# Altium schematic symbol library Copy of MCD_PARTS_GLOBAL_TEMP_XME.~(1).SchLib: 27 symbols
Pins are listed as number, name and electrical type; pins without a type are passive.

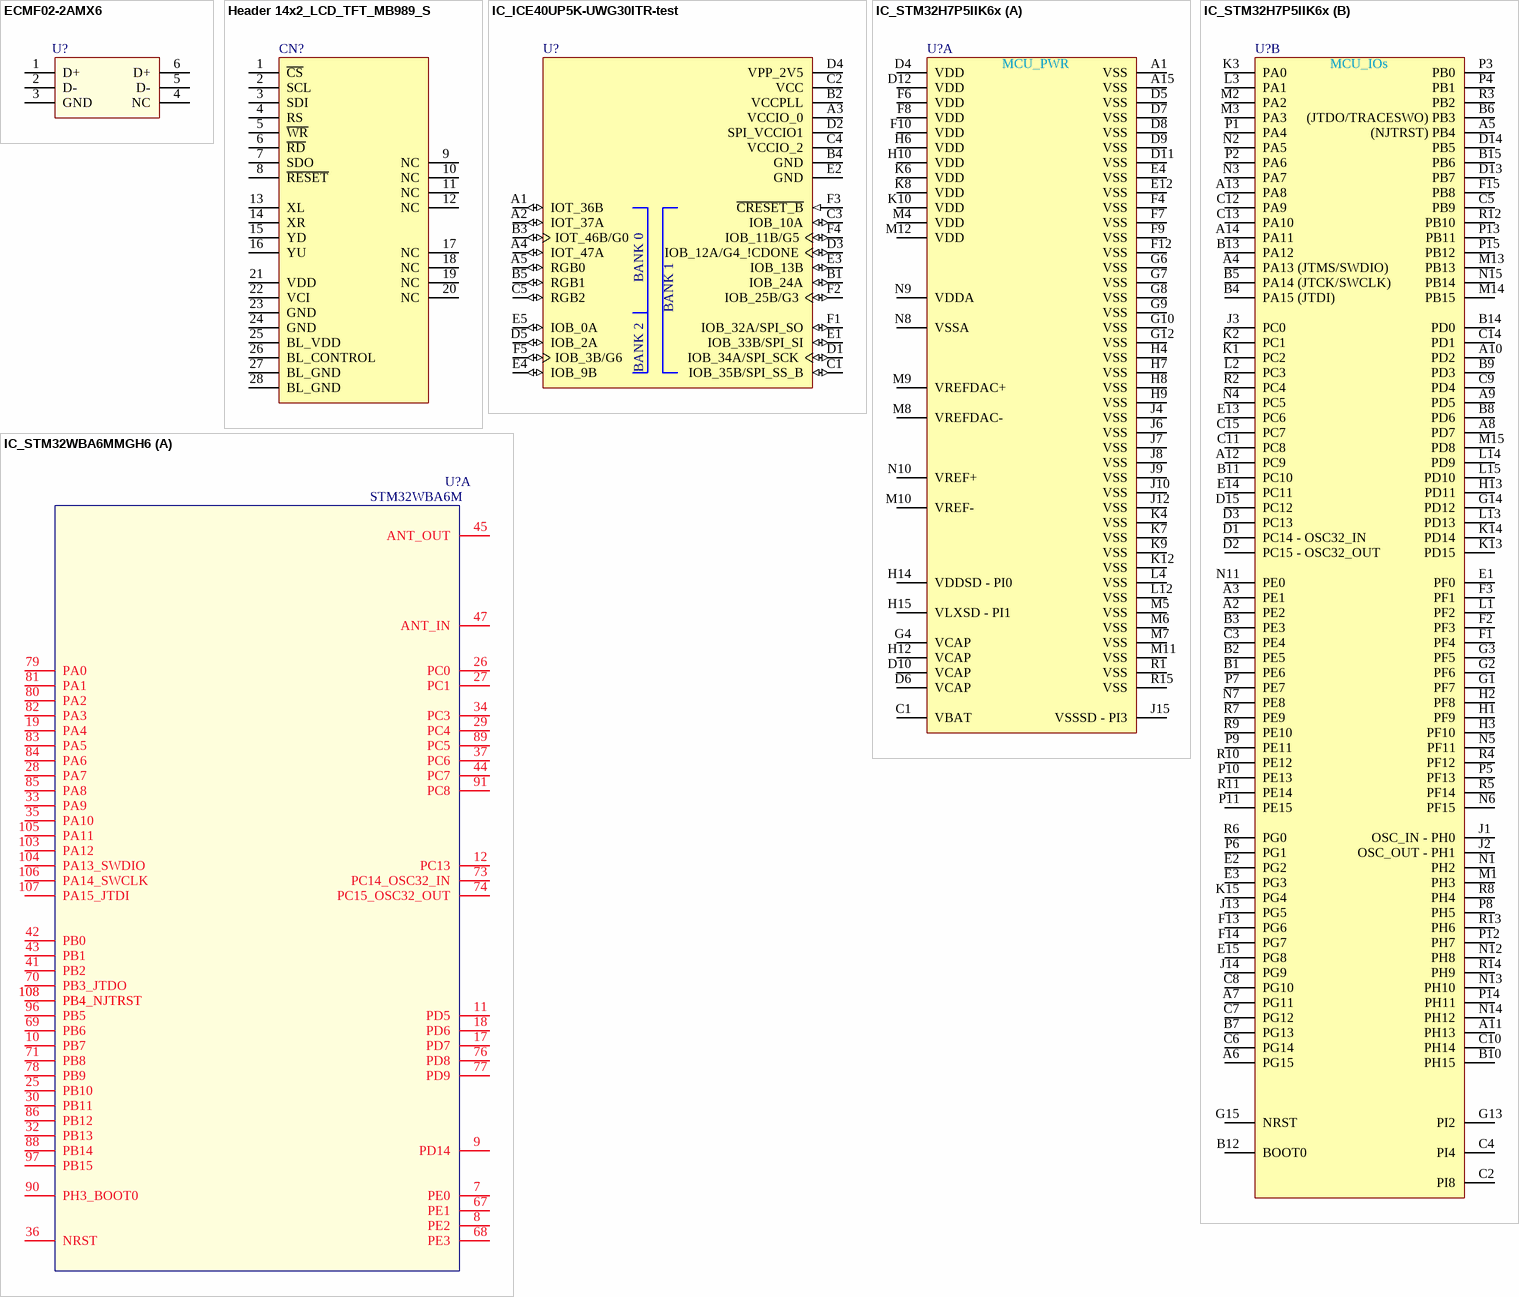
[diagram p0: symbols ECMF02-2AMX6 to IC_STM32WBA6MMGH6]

## ECMF02-2AMX6
designator U?
pins: 1 D+, 2 D-, 3 GND, 4 NC, 5 D-, 6 D+

## Header 14x2_LCD_TFT_MB989_S
designator CN?
pins: 1 ~{CS}, 2 SCL, 3 SDI, 4 RS, 5 ~{WR}, 6 ~{RD}, 7 SDO, 8 ~{RESET}, 9 NC, 10 NC, 11 NC, 12 NC, 13 XL, 14 XR, 15 YD, 16 YU, 17 NC, 18 NC, 19 NC, 20 NC, 21 VDD, 22 VCI, 23 GND, 24 GND, 25 BL_VDD, 26 BL_CONTROL, 27 BL_GND, 28 BL_GND
1 alternate drawing of the same symbol

## IC_ICE40UP5K-UWG30ITR-test
designator U?
Manufacturer: LATTICE SEMICONDUCTOR; Value: ICE40UP5K-UWG30ITR
footprint Model Name (Footprint not found)
footprint Model Name (Footprint not found)
footprint Model Name (Footprint not found)
pins: A1 IOT_36B (io), A2 IOT_37A (io), A3 VCCIO_0, A4 IOT_47A (io), A5 RGB0 (io), B1 IOB_24A (io), B2 VCCPLL, B3 IOT_46B/G0 (io), B4 GND, B5 RGB1 (io), C1 IOB_35B/SPI_SS_B (io), C2 VCC, C3 IOB_10A (io), C4 VCCIO_2, C5 RGB2 (io), D1 IOB_34A/SPI_SCK (io), D2 SPI_VCCIO1, D3 IOB_12A/G4_!CDONE (io), D4 VPP_2V5, D5 IOB_2A (io), E1 IOB_33B/SPI_SI (io), E2 GND, E3 IOB_13B (io), E4 IOB_9B (io), E5 IOB_0A (io), F1 IOB_32A/SPI_SO (io), F2 IOB_25B/G3 (io), F3 ~{CRESET_B} (in), F4 IOB_11B/G5 (io), F5 IOB_3B/G6 (io)

## IC_STM32H7P5IIK6x
designator U?
part A pins: A1 VSS, A15 VSS, C1 VBAT, D4 VDD, D5 VSS, D6 VCAP, D7 VSS, D8 VSS, D9 VSS, D10 VCAP, D11 VSS, D12 VDD, E4 VSS, E12 VSS, F4 VSS, F6 VDD, F7 VSS, F8 VDD, F9 VSS, F10 VDD, F12 VSS, G4 VCAP, G6 VSS, G7 VSS, G8 VSS, G9 VSS, G10 VSS, G12 VSS, H4 VSS, H6 VDD, H7 VSS, H8 VSS, H9 VSS, H10 VDD, H12 VCAP, H14 VDDSD - PI0, H15 VLXSD - PI1, J4 VSS, J6 VSS, J7 VSS, J8 VSS, J9 VSS, J10 VSS, J12 VSS, J15 VSSSD - PI3, K4 VSS, K6 VDD, K7 VSS, K8 VDD, K9 VSS, K10 VDD, K12 VSS, L4 VSS, L12 VSS, M4 VDD, M5 VSS, M6 VSS, M7 VSS, M8 VREFDAC-, M9 VREFDAC+, M10 VREF-, M11 VSS, M12 VDD, N8 VSSA, N9 VDDA, N10 VREF+, R1 VSS, R15 VSS
part B pins: A2 PE2, A3 PE1, A4 PA13 (JTMS/SWDIO), A5 (NJTRST) PB4, A6 PG15, A7 PG11, A8 PD7, A9 PD5, A10 PD2, A11 PH13, A12 PC9, A13 PA8, A14 PA11, B1 PE6, B2 PE5, B3 PE3, B4 PA15 (JTDI), B5 PA14 (JTCK/SWCLK), B6 (JTDO/TRACESWO) PB3, B7 PG13, B8 PD6, B9 PD3, B10 PH15, B11 PC10, B12 BOOT0, B13 PA12, B14 PD0, B15 PB6, C2 PI8, C3 PE4, C4 PI4, C5 PB9, C6 PG14, C7 PG12, C8 PG10, C9 PD4, C10 PH14, C11 PC8, C12 PA9, C13 PA10, C14 PD1, C15 PC7, D1 PC14 - OSC32_IN, D2 PC15 - OSC32_OUT, D3 PC13, D13 PB7, D14 PB5, D15 PC12, E1 PF0, E2 PG2, E3 PG3, E13 PC6, E14 PC11, E15 PG8, F1 PF4, F2 PF3, F3 PF1, F13 PG6, F14 PG7, F15 PB8, G1 PF7, G2 PF6, G3 PF5, G13 PI2, G14 PD12, G15 NRST, H1 PF9, H2 PF8, H3 PF10, H13 PD11, J1 OSC_IN - PH0, J2 OSC_OUT - PH1, J3 PC0, J13 PG5, J14 PG9, K1 PC2, K2 PC1, K3 PA0, K13 PD15, K14 PD14, K15 PG4, L1 PF2, L2 PC3, L3 PA1, L13 PD13, L14 PD9, L15 PD10, M1 PH3, M2 PA2, M3 PA3, M13 PB13, M14 PB15, M15 PD8, N1 PH2, N2 PA5, N3 PA7, N4 PC5, N5 PF11, N6 PF15, N7 PE8, N11 PE0, N12 PH8, N13 PH10, N14 PH12, N15 PB14, P1 PA4, P2 PA6, P3 PB0, P4 PB1, P5 PF13, P6 PG1, P7 PE7, P8 PH5, P9 PE11, P10 PE13, P11 PE15, P12 PH7, P13 PB11, P14 PH11, P15 PB12, R2 PC4, R3 PB2, R4 PF12, R5 PF14, R6 PG0, R7 PE9, R8 PH4, R9 PE10, R10 PE12, R11 PE14, R12 PB10, R13 PH6, R14 PH9
1 alternate drawing of the same symbol

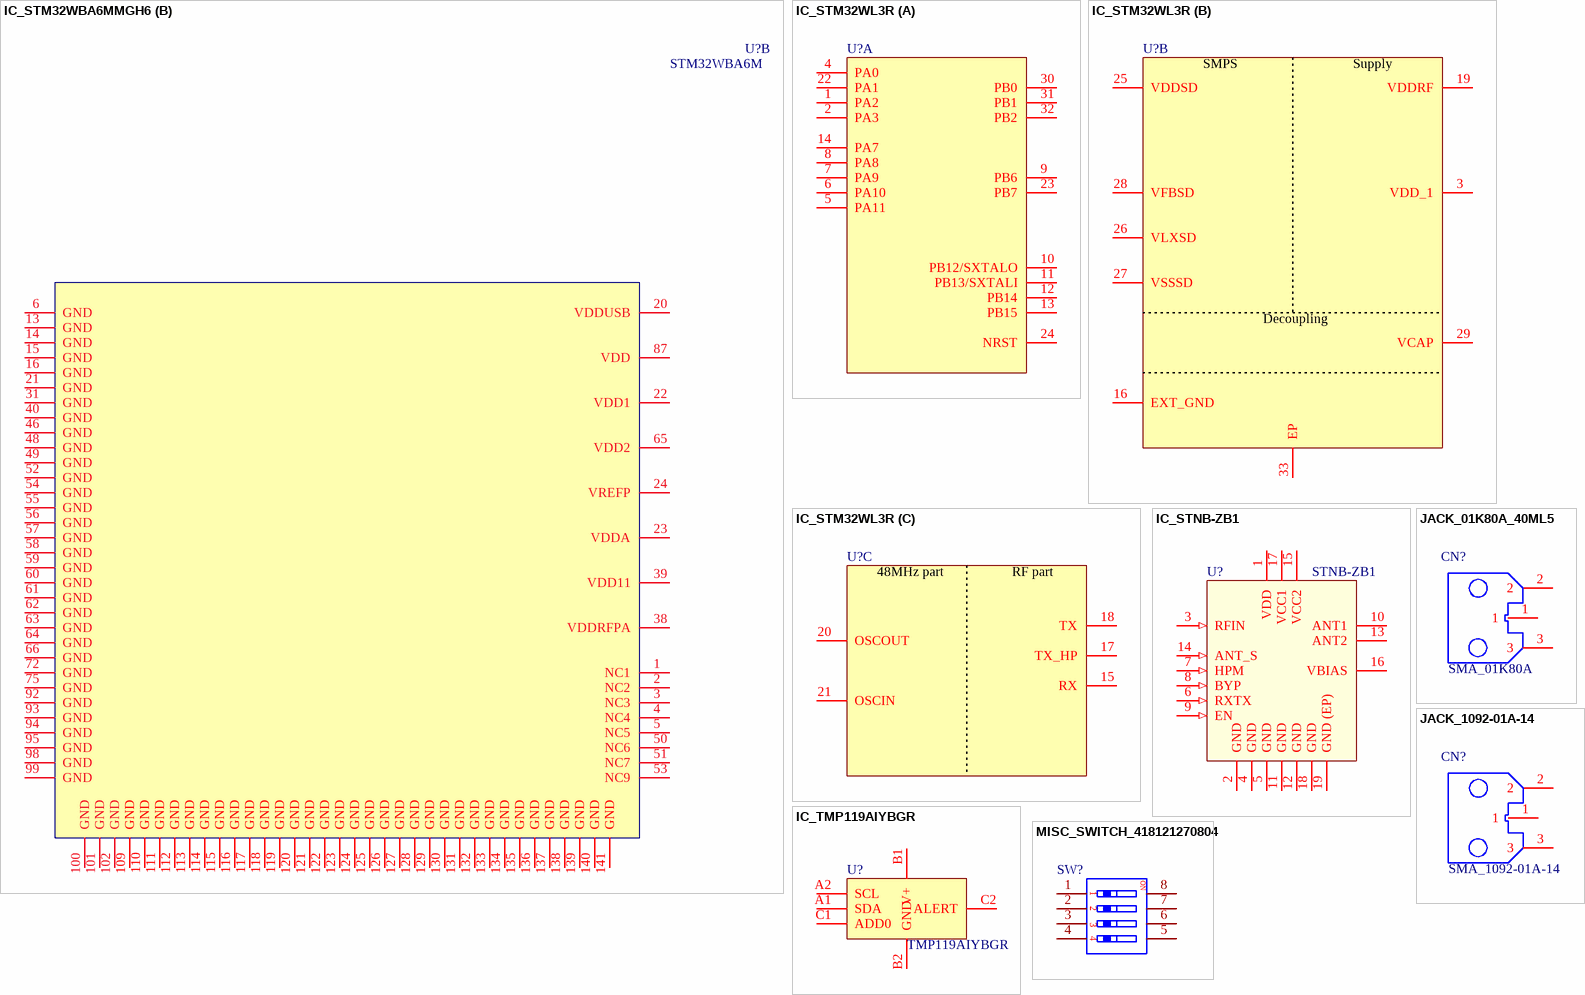
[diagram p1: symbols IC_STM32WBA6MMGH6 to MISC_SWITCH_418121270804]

## IC_STM32WBA6MMGH6
designator U?, comment STM32WBA6M
STM32WBA6M module; Internal_Part_Number: MCD-04297; Manufacturer: STMICROELECTRONICS; Manufacturer_Part_Number: STM32WBA6MMGH6; ECCN_EU: NEC; ECCN_US: EAR99
footprint STM32WBA6M (Footprint not found)
part A pins: 7 PE0, 8 PE2, 9 PD14, 10 PB7, 11 PD5, 12 PC13, 17 PD7, 18 PD6, 19 PA4, 25 PB10, 26 PC0, 27 PC1, 28 PA7, 29 PC4, 30 PB11, 32 PB13, 33 PA9, 34 PC3, 35 PA10, 36 NRST, 37 PC6, 41 PB2, 42 PB0, 43 PB1, 44 PC7, 45 ANT_OUT, 47 ANT_IN, 67 PE1, 68 PE3, 69 PB6, 70 PB3_JTDO, 71 PB8, 73 PC14_OSC32_IN, 74 PC15_OSC32_OUT, 76 PD8, 77 PD9, 78 PB9, 79 PA0, 80 PA2, 81 PA1, 82 PA3, 83 PA5, 84 PA6, 85 PA8, 86 PB12, 88 PB14, 89 PC5, 90 PH3_BOOT0, 91 PC8, 96 PB5, 97 PB15, 103 PA12, 104 PA13_SWDIO, 105 PA11, 106 PA14_SWCLK, 107 PA15_JTDI, 108 PB4_NJTRST
part B pins: 1 NC1, 2 NC2, 3 NC3, 4 NC4, 5 NC5, 6 GND, 13 GND, 14 GND, 15 GND, 16 GND, 20 VDDUSB, 21 GND, 22 VDD1, 23 VDDA, 24 VREFP, 31 GND, 38 VDDRFPA, 39 VDD11, 40 GND, 46 GND, 48 GND, 49 GND, 50 NC6, 51 NC7, 52 GND, 53 NC9, 54 GND, 55 GND, 56 GND, 57 GND, 58 GND, 59 GND, 60 GND, 61 GND, 62 GND, 63 GND, 64 GND, 65 VDD2, 66 GND, 72 GND, 75 GND, 87 VDD, 92 GND, 93 GND, 94 GND, 95 GND, 98 GND, 99 GND, 100 GND, 101 GND, 102 GND, 109 GND, 110 GND, 111 GND, 112 GND, 113 GND, 114 GND, 115 GND, 116 GND, 117 GND, 118 GND, 119 GND, 120 GND, 121 GND, 122 GND, 123 GND, 124 GND, 125 GND, 126 GND, 127 GND, 128 GND, 129 GND, 130 GND, 131 GND, 132 GND, 133 GND, 134 GND, 135 GND, 136 GND, 137 GND, 138 GND, 139 GND, 140 GND, 141 GND

## IC_STM32WL3R
designator U?
part A pins: 1 PA2, 2 PA3, 4 PA0, 5 PA11, 6 PA10, 7 PA9, 8 PA8, 9 PB6, 10 PB12/SXTALO, 11 PB13/SXTALI, 12 PB14, 13 PB15, 14 PA7, 22 PA1, 23 PB7, 24 NRST, 30 PB0, 31 PB1, 32 PB2
part B pins: 3 VDD_1, 16 EXT_GND, 19 VDDRF, 25 VDDSD, 26 VLXSD, 27 VSSSD, 28 VFBSD, 29 VCAP, 33 EP
part C pins: 15 RX, 17 TX_HP, 18 TX, 20 OSCOUT, 21 OSCIN

## IC_STNB-ZB1
designator U?  value STNB-ZB1
pins: 1 VDD (power), 2 GND, 3 RFIN (in), 4 GND, 5 GND, 6 RXTX (in), 7 HPM (in), 8 BYP (in), 9 EN (in), 10 ANT1, 11 GND, 12 GND, 13 ANT2, 14 ANT_S (in), 15 VCC2, 16 VBIAS, 17 VCC1 (power), 18 GND, 19 GND (EP)
1 alternate drawing of the same symbol

## IC_TMP119AIYBGR
designator U?, comment value TMP119AIYBGR  (hidden comment: SN74AUC1G17DBVR)
pins: A1 SDA, A2 SCL, B1 V+, B2 GND, C1 ADD0, C2 ALERT (oc)

## JACK_01K80A_40ML5
designator CN?, comment SMA_01K80A
PCB connector 30° 1mm connector
footprint Model Name (Footprint not found)
footprint Rosenberger_08K80F (RF conn 1.85mm)
footprint Rosenberger_08K80F (RF conn 1.85mm)
footprint Rosenberger_08K80F (RF conn 1.85mm)
footprint Rosenberger_08K80F (RF conn 1.85mm)
footprint Rosenberger_08K80F (RF conn 1.85mm)
footprint Rosenberger_08K80F_v2 (RF conn 1.85mm)
footprint Rosenberger_08K80F_v2 (RF conn 1.85mm)
footprint Rosenberger_08K80F_v2 (RF conn 1.85mm)
footprint Rosenberger_08K80F_v2 (RF conn 1.85mm)
footprint Rosenberger_08K80F_v2 (RF conn 1.85mm)
footprint Rosenberger_08K80F_v2 (RF conn 1.85mm)
footprint Rosenberger_08K80F_v2 (RF conn 1.85mm)
footprint Rosenberger_08K80F_v2 (RF conn 1.85mm)
footprint Rosenberger_08K80F_v2 (RF conn 1.85mm)
footprint Rosenberger_08K80F_v2 (RF conn 1.85mm)
footprint Rosenberger_08K80F_v2 (RF conn 1.85mm)
footprint Rosenberger_08K80F_v2 (RF conn 1.85mm)
footprint Rosenberger_08K80F_v2 (RF conn 1.85mm)
footprint Rosenberger_08K80F_v2 (RF conn 1.85mm)
footprint Rosenberger_08K80F_v2 (RF conn 1.85mm)
footprint Rosenberger_08K80F_v2 (RF conn 1.85mm)
footprint Rosenberger_08K80F_v2 (RF conn 1.85mm)
footprint Rosenberger_08K80F_v2 (RF conn 1.85mm)
footprint Rosenberger_08K80F_v2 (RF conn 1.85mm)
footprint Rosenberger_08K80F_v2 (RF conn 1.85mm)
footprint Rosenberger_08K80F_v2 (RF conn 1.85mm)
footprint Rosenberger_08K80F_v2 (RF conn 1.85mm)
footprint Rosenberger_08K80F_v2 (RF conn 1.85mm)
footprint Rosenberger_08K80F_v2 (RF conn 1.85mm)
pins: 1, 2, 3

## JACK_1092-01A-14
designator CN?, comment SMA_1092-01A-14
footprint Model Name (Footprint not found)
footprint Rosenberger_08K80F (RF conn 1.85mm)
footprint Rosenberger_08K80F (RF conn 1.85mm)
footprint Rosenberger_08K80F (RF conn 1.85mm)
footprint Rosenberger_08K80F (RF conn 1.85mm)
footprint Rosenberger_08K80F (RF conn 1.85mm)
footprint Rosenberger_08K80F_v2 (RF conn 1.85mm)
footprint Rosenberger_08K80F_v2 (RF conn 1.85mm)
footprint Rosenberger_08K80F_v2 (RF conn 1.85mm)
footprint Rosenberger_08K80F_v2 (RF conn 1.85mm)
footprint Rosenberger_08K80F_v2 (RF conn 1.85mm)
footprint Rosenberger_08K80F_v2 (RF conn 1.85mm)
footprint Rosenberger_08K80F_v2 (RF conn 1.85mm)
footprint Rosenberger_08K80F_v2 (RF conn 1.85mm)
footprint Rosenberger_08K80F_v2 (RF conn 1.85mm)
footprint Rosenberger_08K80F_v2 (RF conn 1.85mm)
footprint Rosenberger_08K80F_v2 (RF conn 1.85mm)
footprint Rosenberger_08K80F_v2 (RF conn 1.85mm)
footprint Rosenberger_08K80F_v2 (RF conn 1.85mm)
footprint Rosenberger_08K80F_v2 (RF conn 1.85mm)
footprint Rosenberger_08K80F_v2 (RF conn 1.85mm)
footprint Rosenberger_08K80F_v2 (RF conn 1.85mm)
footprint Rosenberger_08K80F_v2 (RF conn 1.85mm)
footprint Rosenberger_08K80F_v2 (RF conn 1.85mm)
footprint Rosenberger_08K80F_v2 (RF conn 1.85mm)
footprint Rosenberger_08K80F_v2 (RF conn 1.85mm)
footprint Rosenberger_08K80F_v2 (RF conn 1.85mm)
footprint Rosenberger_08K80F_v2 (RF conn 1.85mm)
footprint Rosenberger_08K80F_v2 (RF conn 1.85mm)
footprint Rosenberger_08K80F_v2 (RF conn 1.85mm)
pins: 1, 2, 3

## MISC_SWITCH_418121270804
designator SW?
Switch 4 slides DIP, SPST, 24V, 25mA, 9.8x11.1mm
pins: 1, 2, 3, 4, 5, 6, 7, 8

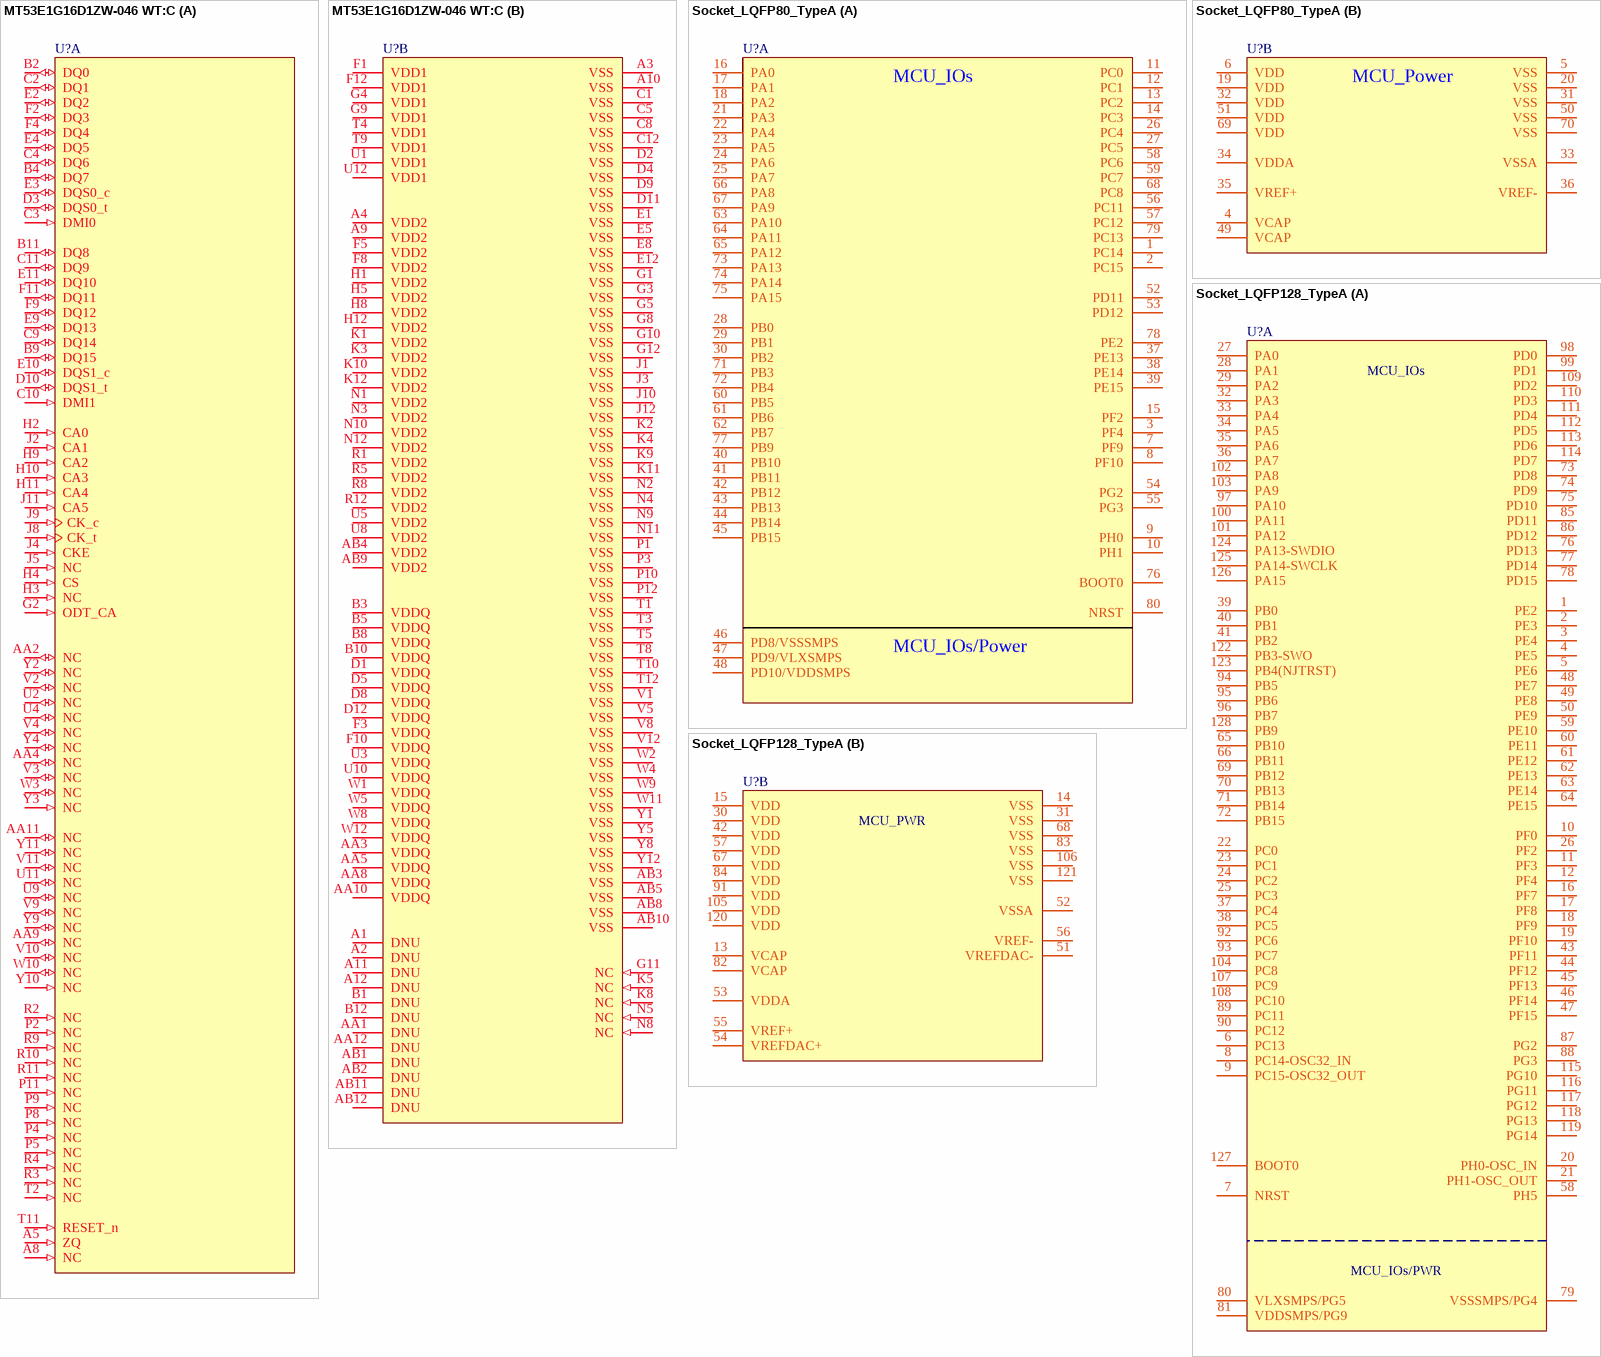
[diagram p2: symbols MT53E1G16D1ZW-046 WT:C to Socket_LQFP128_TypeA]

## MT53E1G16D1ZW-046 WT:C
designator U?
part A pins: A5 ZQ (in) "External impedance (240 ohm): This signal is used to calibrate the device output impedance.", A8 NC (in), AA2 NC (io) "Data input/output: Bidirectional data bus.", AA4 NC (io) "Data input/output: Bidirectional data bus.", AA9 NC (io) "Data input/output: Bidirectional data bus.", AA11 NC (io) "Data input/output: Bidirectional data bus.", B2 DQ0 (io) "Data input/output: Bidirectional data bus.", B4 DQ7 (io) "Data input/output: Bidirectional data bus.", B9 DQ15 (io) "Data input/output: Bidirectional data bus.", B11 DQ8 (io) "Data input/output: Bidirectional data bus.", C2 DQ1 (io) "Data input/output: Bidirectional data bus.", C3 DMI0 (in) "Input data mask: DM is an input mask signal for write data. Although DM ballsare input-only, the DM loading is designed to match that of DQ and DQS balls.DM[3:0] is DM for each of the four data bytes, respectively.", C4 DQ6 (io) "Data input/output: Bidirectional data bus.", C9 DQ14 (io) "Data input/output: Bidirectional data bus.", C10 DMI1 (in) "Input data mask: DM is an input mask signal for write data. Although DM ballsare input-only, the DM loading is designed to match that of DQ and DQS balls.DM[3:0] is DM for each of the four data bytes, respectively.", C11 DQ9 (io) "Data input/output: Bidirectional data bus.", D3 DQS0_t (io) "Data strobe: The data strobe is bidirectional (used for read and write data) andcomplementary (DQS and DQS#). It is edge-aligned output with read data andcentered input with write data. DQS[3:0]/DQS[3:0]# is DQS for each of (See Datasheet)", D10 DQS1_t (io) "Data strobe: The data strobe is bidirectional (used for read and write data) andcomplementary (DQS and DQS#). It is edge-aligned output with read data andcentered input with write data. DQS[3:0]/DQS[3:0]# is DQS for each of (See Datasheet)", E2 DQ2 (io) "Data input/output: Bidirectional data bus.", E3 DQS0_c (io) "Data strobe: The data strobe is bidirectional (used for read and write data) andcomplementary (DQS and DQS#). It is edge-aligned output with read data andcentered input with write data. DQS[3:0]/DQS[3:0]# is DQS for each of (See Datasheet)", E4 DQ5 (io) "Data input/output: Bidirectional data bus.", E9 DQ13 (io) "Data input/output: Bidirectional data bus.", E10 DQS1_c (io) "Data strobe: The data strobe is bidirectional (used for read and write data) andcomplementary (DQS and DQS#). It is edge-aligned output with read data andcentered input with write data. DQS[3:0]/DQS[3:0]# is DQS for each of (See Datasheet)", E11 DQ10 (io) "Data input/output: Bidirectional data bus.", F2 DQ3 (io) "Data input/output: Bidirectional data bus.", F4 DQ4 (io) "Data input/output: Bidirectional data bus.", F9 DQ12 (io) "Data input/output: Bidirectional data bus.", F11 DQ11 (io) "Data input/output: Bidirectional data bus.", G2 ODT_CA (in) "on die termination on CA", H2 CA0 (in) "Command/address inputs: Provide the command and address inputs accordingto the command truth table.", H3 NC (in), H4 CS (in) "Chip select: CS# is considered part of the command code and is sampled at therising edge of CK.", H9 CA2 (in) "Command/address inputs: Provide the command and address inputs accordingto the command truth table.", H10 CA3 (in) "Command/address inputs: Provide the command and address inputs accordingto the command truth table.", H11 CA4 (in) "Command/address inputs: Provide the command and address inputs accordingto the command truth table.", J2 CA1 (in) "Command/address inputs: Provide the command and address inputs accordingto the command truth table.", J4 CKE (in) "Clock enable: CKE HIGH activates and CKE LOW deactivates the internal clocksignals, input buffers, and output drivers. Power-saving modes are entered andexited via CKE transitions. CKE is considered part of the command code. (See Datasheet)", J5 NC (in), J8 CK_t (in) "Clock: CK and CK# are differential clock inputs. All CA inputs are sampled onboth rising and falling edges of CK. CS and CKE inputs are sampled at the risingedge of CK. AC timings are referenced to clock.", J9 CK_c (in) "Clock: CK and CK# are differential clock inputs. All CA inputs are sampled onboth rising and falling edges of CK. CS and CKE inputs are sampled at the risingedge of CK. AC timings are referenced to clock.", J11 CA5 (in) "Command/address inputs: Provide the command and address inputs accordingto the command truth table.", P2 NC (in) "Command/address inputs: Provide the command and address inputs accordingto the command truth table.", P4 NC (in) "Clock enable: CKE HIGH activates and CKE LOW deactivates the internal clocksignals, input buffers, and output drivers. Power-saving modes are entered andexited via CKE transitions. CKE is considered part of the command code. (See Datasheet)", P5 NC (in), P8 NC (in) "Clock: CK and CK# are differential clock inputs. All CA inputs are sampled onboth rising and falling edges of CK. CS and CKE inputs are sampled at the risingedge of CK. AC timings are referenced to clock.", P9 NC (in) "Clock: CK and CK# are differential clock inputs. All CA inputs are sampled onboth rising and falling edges of CK. CS and CKE inputs are sampled at the risingedge of CK. AC timings are referenced to clock.", P11 NC (in) "Command/address inputs: Provide the command and address inputs accordingto the command truth table.", R2 NC (in) "Command/address inputs: Provide the command and address inputs accordingto the command truth table.", R3 NC (in), R4 NC (in) "Chip select: CS# is considered part of the command code and is sampled at therising edge of CK.", R9 NC (in) "Command/address inputs: Provide the command and address inputs accordingto the command truth table.", R10 NC (in) "Command/address inputs: Provide the command and address inputs accordingto the command truth table.", R11 NC (in) "Command/address inputs: Provide the command and address inputs accordingto the command truth table.", T2 NC (in) "on die termination on CA", T11 RESET_n (in) "Reset active low", U2 NC (io) "Data input/output: Bidirectional data bus.", U4 NC (io) "Data input/output: Bidirectional data bus.", U9 NC (io) "Data input/output: Bidirectional data bus.", U11 NC (io) "Data input/output: Bidirectional data bus.", V2 NC (io) "Data input/output: Bidirectional data bus.", V3 NC (io) "Data strobe: The data strobe is bidirectional (used for read and write data) andcomplementary (DQS and DQS#). It is edge-aligned output with read data andcentered input with write data. DQS[3:0]/DQS[3:0]# is DQS for each of (See Datasheet)", V4 NC (io) "Data input/output: Bidirectional data bus.", V9 NC (io) "Data input/output: Bidirectional data bus.", V10 NC (io) "Data strobe: The data strobe is bidirectional (used for read and write data) andcomplementary (DQS and DQS#). It is edge-aligned output with read data andcentered input with write data. DQS[3:0]/DQS[3:0]# is DQS for each of (See Datasheet)", V11 NC (io) "Data input/output: Bidirectional data bus.", W3 NC (io) "Data strobe: The data strobe is bidirectional (used for read and write data) andcomplementary (DQS and DQS#). It is edge-aligned output with read data andcentered input with write data. DQS[3:0]/DQS[3:0]# is DQS for each of (See Datasheet)", W10 NC (io) "Data strobe: The data strobe is bidirectional (used for read and write data) andcomplementary (DQS and DQS#). It is edge-aligned output with read data andcentered input with write data. DQS[3:0]/DQS[3:0]# is DQS for each of (See Datasheet)", Y2 NC (io) "Data input/output: Bidirectional data bus.", Y3 NC (in) "Input data mask: DM is an input mask signal for write data. Although DM ballsare input-only, the DM loading is designed to match that of DQ and DQS balls.DM[3:0] is DM for each of the four data bytes, respectively.", Y4 NC (io) "Data input/output: Bidirectional data bus.", Y9 NC (io) "Data input/output: Bidirectional data bus.", Y10 NC (in) "Input data mask: DM is an input mask signal for write data. Although DM ballsare input-only, the DM loading is designed to match that of DQ and DQS balls.DM[3:0] is DM for each of the four data bytes, respectively.", Y11 NC (io) "Data input/output: Bidirectional data bus."
part B pins: A1 DNU "Do not use: Must be grounded or left floating.", A2 DNU "Do not use: Must be grounded or left floating.", A3 VSS (power) "Common ground.", A4 VDD2 (power) "Core power: Supply 2.", A9 VDD2 (power) "Core power: Supply 2.", A10 VSS (power) "Common ground.", A11 DNU "Do not use: Must be grounded or left floating.", A12 DNU "Do not use: Must be grounded or left floating.", AA1 DNU "Do not use: Must be grounded or left floating.", AA3 VDDQ (power) "DQ power supply: Isolated on the die for improved noise immunity.", AA5 VDDQ (power) "DQ power supply: Isolated on the die for improved noise immunity.", AA8 VDDQ (power) "DQ power supply: Isolated on the die for improved noise immunity.", AA10 VDDQ (power) "DQ power supply: Isolated on the die for improved noise immunity.", AA12 DNU "Do not use: Must be grounded or left floating.", AB1 DNU "Do not use: Must be grounded or left floating.", AB2 DNU "Do not use: Must be grounded or left floating.", AB3 VSS "Common ground.", AB4 VDD2 (power) "Core power: Supply 2.", AB5 VSS "Common ground.", AB8 VSS "Common ground.", AB9 VDD2 (power) "Core power: Supply 2.", AB10 VSS "Common ground.", AB11 DNU "Do not use: Must be grounded or left floating.", AB12 DNU "Do not use: Must be grounded or left floating.", B1 DNU "Do not use: Must be grounded or left floating.", B3 VDDQ (power) "DQ power supply: Isolated on the die for improved noise immunity.", B5 VDDQ (power) "DQ power supply: Isolated on the die for improved noise immunity.", B8 VDDQ (power) "DQ power supply: Isolated on the die for improved noise immunity.", B10 VDDQ (power) "DQ power supply: Isolated on the die for improved noise immunity.", B12 DNU "Do not use: Must be grounded or left floating.", C1 VSS (power) "Common ground.", C5 VSS (power) "Common ground.", C8 VSS (power) "Common ground.", C12 VSS (power) "Common ground.", D1 VDDQ (power) "DQ power supply: Isolated on the die for improved noise immunity.", D2 VSS (power) "Common ground.", D4 VSS (power) "Common ground.", D5 VDDQ (power) "DQ power supply: Isolated on the die for improved noise immunity.", D8 VDDQ (power) "DQ power supply: Isolated on the die for improved noise immunity.", D9 VSS (power) "Common ground.", D11 VSS (power) "Common ground.", D12 VDDQ (power) "DQ power supply: Isolated on the die for improved noise immunity.", E1 VSS (power) "Common ground.", E5 VSS (power) "Common ground.", E8 VSS (power) "Common ground.", E12 VSS (power) "Common ground.", F1 VDD1 (power) "Core power: Supply 1.", F3 VDDQ (power) "DQ power supply: Isolated on the die for improved noise immunity.", F5 VDD2 (power) "Core power: Supply 2.", F8 VDD2 (power) "Core power: Supply 2.", F10 VDDQ (power) "DQ power supply: Isolated on the die for improved noise immunity.", F12 VDD1 (power) "Core power: Supply 1.", G1 VSS (power) "Common ground.", G3 VSS (power) "Common ground.", G4 VDD1 (power) "Core power: Supply 1.", G5 VSS (power) "Common ground.", G8 VSS (power) "Common ground.", G9 VDD1 (power) "Core power: Supply 1.", G10 VSS (power) "Common ground.", G11 NC (in) "Not connected", G12 VSS (power) "Common ground.", H1 VDD2 (power) "Core power: Supply 2.", H5 VDD2 (power) "Core power: Supply 2.", H8 VDD2 (power) "Core power: Supply 2.", H12 VDD2 (power) "Core power: Supply 2.", J1 VSS (power) "Common ground.", J3 VSS (power) "Common ground.", J10 VSS (power) "Common ground.", J12 VSS (power) "Common ground.", K1 VDD2 (power) "Core power: Supply 2.", K2 VSS (power) "Common ground.", K3 VDD2 (power) "Core power: Supply 2.", K4 VSS (power) "Common ground.", K5 NC (in) "Not connected", K8 NC (in) "Not connected", K9 VSS (power) "Common ground.", K10 VDD2 (power) "Core power: Supply 2.", K11 VSS "Common ground.", K12 VDD2 (power) "Core power: Supply 2.", N1 VDD2 (power) "Core power: Supply 2.", N2 VSS "Common ground.", N3 VDD2 (power) "Core power: Supply 2.", N4 VSS "Common ground.", N5 NC (in) "Not connected", N8 NC (in) "Not connected", N9 VSS "Common ground.", N10 VDD2 (power) "Core power: Supply 2.", N11 VSS "Common ground.", N12 VDD2 (power) "Core power: Supply 2.", P1 VSS "Common ground.", P3 VSS (power) "Common ground.", P10 VSS (power) "Common ground.", P12 VSS "Common ground.", R1 VDD2 (power) "Core power: Supply 2.", R5 VDD2 (power) "Core power: Supply 2.", R8 VDD2 (power) "Core power: Supply 2.", R12 VDD2 (power) "Core power: Supply 2.", T1 VSS "Common ground.", T3 VSS "Common ground.", T4 VDD1 (power) "Core power: Supply 1.", T5 VSS "Common ground.", T8 VSS "Common ground.", T9 VDD1 (power) "Core power: Supply 1.", T10 VSS "Common ground.", T12 VSS "Common ground.", U1 VDD1 (power) "Core power: Supply 1.", U3 VDDQ (power) "DQ power supply: Isolated on the die for improved noise immunity.", U5 VDD2 (power) "Core power: Supply 2.", U8 VDD2 (power) "Core power: Supply 2.", U10 VDDQ (power) "DQ power supply: Isolated on the die for improved noise immunity.", U12 VDD1 (power) "Core power: Supply 1.", V1 VSS (power) "Common ground.", V5 VSS (power) "Common ground.", V8 VSS "Common ground.", V12 VSS "Common ground.", W1 VDDQ (power) "DQ power supply: Isolated on the die for improved noise immunity.", W2 VSS "Common ground.", W4 VSS "Common ground.", W5 VDDQ (power) "DQ power supply: Isolated on the die for improved noise immunity.", W8 VDDQ (power) "DQ power supply: Isolated on the die for improved noise immunity.", W9 VSS "Common ground.", W11 VSS "Common ground.", W12 VDDQ (power) "DQ power supply: Isolated on the die for improved noise immunity.", Y1 VSS "Common ground.", Y5 VSS "Common ground.", Y8 VSS "Common ground.", Y12 VSS "Common ground."

## Socket_LQFP80_TypeA
designator U?
part A pins: 1 PC14, 2 PC15, 3 PF4, 7 PF9, 8 PF10, 9 PH0, 10 PH1, 11 PC0, 12 PC1, 13 PC2, 14 PC3, 15 PF2, 16 PA0, 17 PA1, 18 PA2, 21 PA3, 22 PA4, 23 PA5, 24 PA6, 25 PA7, 26 PC4, 27 PC5, 28 PB0, 29 PB1, 30 PB2, 37 PE13, 38 PE14, 39 PE15, 40 PB10, 41 PB11, 42 PB12, 43 PB13, 44 PB14, 45 PB15, 46 PD8/VSSSMPS, 47 PD9/VLXSMPS, 48 PD10/VDDSMPS, 52 PD11, 53 PD12, 54 PG2, 55 PG3, 56 PC11, 57 PC12, 58 PC6, 59 PC7, 60 PB5, 61 PB6, 62 PB7, 63 PA10, 64 PA11, 65 PA12, 66 PA8, 67 PA9, 68 PC8, 71 PB3, 72 PB4, 73 PA13, 74 PA14, 75 PA15, 76 BOOT0, 77 PB9, 78 PE2, 79 PC13, 80 NRST
part B pins: 4 VCAP, 5 VSS, 6 VDD, 19 VDD, 20 VSS, 31 VSS, 32 VDD, 33 VSSA, 34 VDDA, 35 VREF+, 36 VREF-, 49 VCAP, 50 VSS, 51 VDD, 69 VDD, 70 VSS

## Socket_LQFP128_TypeA
designator U?
part A pins: 1 PE2, 2 PE3, 3 PE4, 4 PE5, 5 PE6, 6 PC13, 7 NRST, 8 PC14-OSC32_IN, 9 PC15-OSC32_OUT, 10 PF0, 11 PF3, 12 PF4, 16 PF7, 17 PF8, 18 PF9, 19 PF10, 20 PH0-OSC_IN, 21 PH1-OSC_OUT, 22 PC0, 23 PC1, 24 PC2, 25 PC3, 26 PF2, 27 PA0, 28 PA1, 29 PA2, 32 PA3, 33 PA4, 34 PA5, 35 PA6, 36 PA7, 37 PC4, 38 PC5, 39 PB0, 40 PB1, 41 PB2, 43 PF11, 44 PF12, 45 PF13, 46 PF14, 47 PF15, 48 PE7, 49 PE8, 50 PE9, 58 PH5, 59 PE10, 60 PE11, 61 PE12, 62 PE13, 63 PE14, 64 PE15, 65 PB10, 66 PB11, 69 PB12, 70 PB13, 71 PB14, 72 PB15, 73 PD8, 74 PD9, 75 PD10, 76 PD13, 77 PD14, 78 PD15, 79 VSSSMPS/PG4, 80 VLXSMPS/PG5, 81 VDDSMPS/PG9, 85 PD11, 86 PD12, 87 PG2, 88 PG3, 89 PC11, 90 PC12, 92 PC6, 93 PC7, 94 PB5, 95 PB6, 96 PB7, 97 PA10, 98 PD0, 99 PD1, 100 PA11, 101 PA12, 102 PA8, 103 PA9, 104 PC8, 107 PC9, 108 PC10, 109 PD2, 110 PD3, 111 PD4, 112 PD5, 113 PD6, 114 PD7, 115 PG10, 116 PG11, 117 PG12, 118 PG13, 119 PG14, 122 PB3-SWO, 123 PB4(NJTRST), 124 PA13-SWDIO, 125 PA14-SWCLK, 126 PA15, 127 BOOT0, 128 PB9
part B pins: 13 VCAP, 14 VSS, 15 VDD, 30 VDD, 31 VSS, 42 VDD, 51 VREFDAC-, 52 VSSA, 53 VDDA, 54 VREFDAC+, 55 VREF+, 56 VREF-, 57 VDD, 67 VDD, 68 VSS, 82 VCAP, 83 VSS, 84 VDD, 91 VDD, 105 VDD, 106 VSS, 120 VDD, 121 VSS

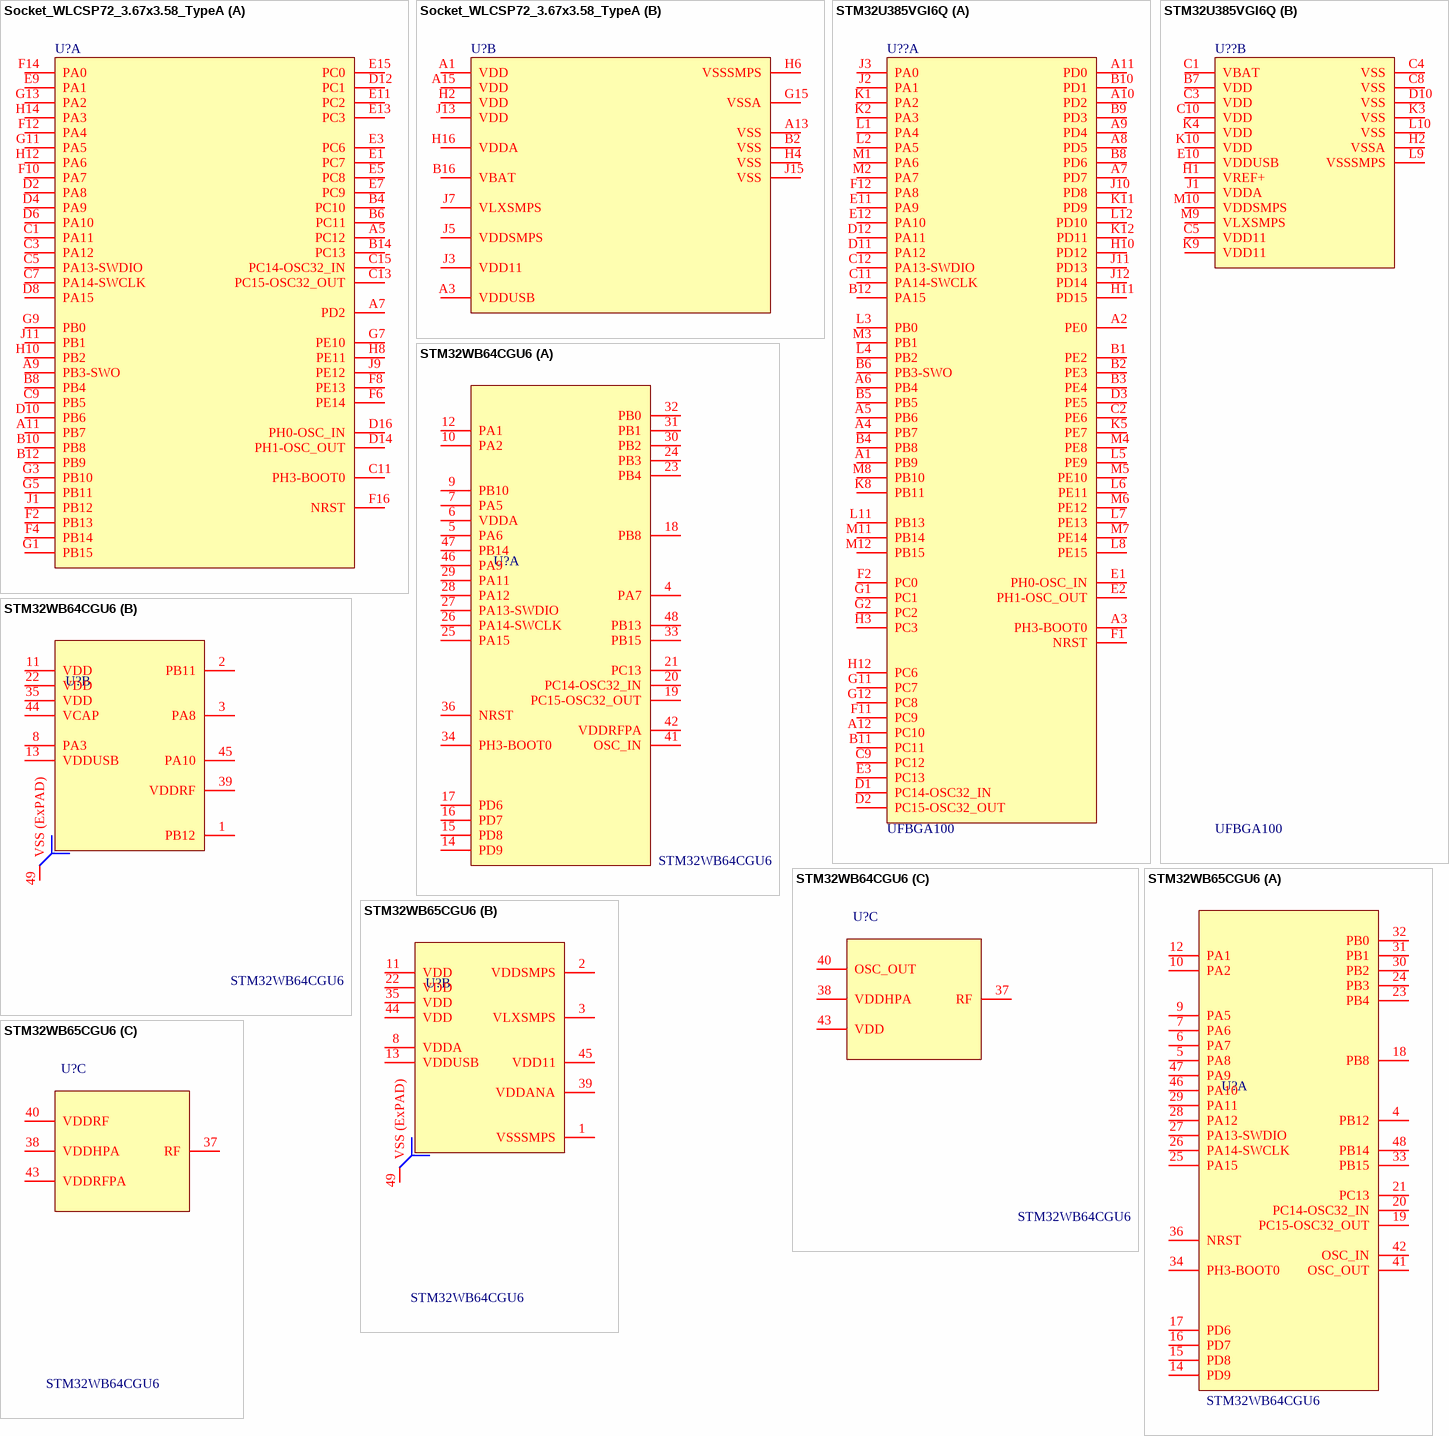
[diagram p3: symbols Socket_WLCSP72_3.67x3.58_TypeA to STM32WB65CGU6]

## Socket_WLCSP72_3.67x3.58_TypeA
designator U?
part A pins: A5 PC12, A7 PD2, A9 PB3-SWO, A11 PB7, B4 PC10, B6 PC11, B8 PB4, B10 PB8, B12 PB9, B14 PC13, C1 PA11, C3 PA12, C5 PA13-SWDIO, C7 PA14-SWCLK, C9 PB5, C11 PH3-BOOT0, C13 PC15-OSC32_OUT, C15 PC14-OSC32_IN, D2 PA8, D4 PA9, D6 PA10, D8 PA15, D10 PB6, D12 PC1, D14 PH1-OSC_OUT, D16 PH0-OSC_IN, E1 PC7, E3 PC6, E5 PC8, E7 PC9, E9 PA1, E11 PC2, E13 PC3, E15 PC0, F2 PB13, F4 PB14, F6 PE14, F8 PE13, F10 PA7, F12 PA4, F14 PA0, F16 NRST, G1 PB15, G3 PB10, G5 PB11, G7 PE10, G9 PB0, G11 PA5, G13 PA2, H8 PE11, H10 PB2, H12 PA6, H14 PA3, J1 PB12, J9 PE12, J11 PB1
part B pins: A1 VDD, A3 VDDUSB, A13 VSS, A15 VDD, B2 VSS, B16 VBAT, G15 VSSA, H2 VDD, H4 VSS, H6 VSSSMPS, H16 VDDA, J3 VDD11, J5 VDDSMPS, J7 VLXSMPS, J13 VDD, J15 VSS

## STM32U385VGI6Q
designator U??  value UFBGA100  (hidden comment: STM32U385VGI6Q)
MCU, ARM Cortex-M33 32-bit, 1MB Flash, 256KB SRAM, TrustZone and FPU, SMPS; Internal_Part_Number: MCD-03201; Part_Type: Socket_IC; Manufacturer_Part_Number: NP584-100-204; Manufacturer: YAMAICHI; Part_Preference: Recommended; Component_Country_Of_Origin: Unknown; ShowFields: YES; ID: 5317
part A pins: A1 PB9, A2 PE0, A3 PH3-BOOT0, A4 PB7, A5 PB6, A6 PB4, A7 PD7, A8 PD5, A9 PD4, A10 PD2, A11 PD0, A12 PC10, B1 PE2, B2 PE3, B3 PE4, B4 PB8, B5 PB5, B6 PB3-SWO, B8 PD6, B9 PD3, B10 PD1, B11 PC11, B12 PA15, C2 PE6, C9 PC12, C11 PA14-SWCLK, C12 PA13-SWDIO, D1 PC14-OSC32_IN, D2 PC15-OSC32_OUT, D3 PE5, D11 PA12, D12 PA11, E1 PH0-OSC_IN, E2 PH1-OSC_OUT, E3 PC13, E11 PA9, E12 PA10, F1 NRST, F2 PC0, F11 PC9, F12 PA8, G1 PC1, G2 PC2, G11 PC7, G12 PC8, H3 PC3, H10 PD12, H11 PD15, H12 PC6, J2 PA1, J3 PA0, J10 PD8, J11 PD13, J12 PD14, K1 PA2, K2 PA3, K5 PE7, K8 PB11, K11 PD9, K12 PD11, L1 PA4, L2 PA5, L3 PB0, L4 PB2, L5 PE9, L6 PE11, L7 PE13, L8 PE15, L11 PB13, L12 PD10, M1 PA6, M2 PA7, M3 PB1, M4 PE8, M5 PE10, M6 PE12, M7 PE14, M8 PB10, M11 PB14, M12 PB15
part B pins: B7 VDD, C1 VBAT, C3 VDD, C4 VSS, C5 VDD11, C8 VSS, C10 VDD, D10 VSS, E10 VDDUSB, H1 VREF+, H2 VSSA, J1 VDDA, K3 VSS, K4 VDD, K9 VDD11, K10 VDD, L9 VSSSMPS, L10 VSS, M9 VLXSMPS, M10 VDDSMPS

## STM32WB64CGU6
designator U?
STM32WB64CGU6_  QFN48_USB_LDO
footprint STM32WB64CGU6 (STM32WB64CGU6   QFN48  USB  LDO)
part A pins: 4 PA7, 5 PA6, 6 VDDA, 7 PA5, 9 PB10, 10 PA2, 12 PA1, 14 PD9, 15 PD8, 16 PD7, 17 PD6, 18 PB8, 19 PC15-OSC32_OUT, 20 PC14-OSC32_IN, 21 PC13, 23 PB4, 24 PB3, 25 PA15, 26 PA14-SWCLK, 27 PA13-SWDIO, 28 PA12, 29 PA11, 30 PB2, 31 PB1, 32 PB0, 33 PB15, 34 PH3-BOOT0, 36 NRST, 41 OSC_IN, 42 VDDRFPA, 46 PA9, 47 PB14, 48 PB13
part B pins: 1 PB12, 2 PB11, 3 PA8, 8 PA3, 11 VDD, 13 VDDUSB, 22 VDD, 35 VDD, 39 VDDRF, 44 VCAP, 45 PA10, 49 VSS (ExPAD)
part C pins: 37 RF, 38 VDDHPA, 40 OSC_OUT, 43 VDD

## STM32WB65CGU6
designator U?, comment STM32WB64CGU6
STM32WB65CGU6  QFN48
footprint STM32WB65CGU6 (STM32WB65CGU6   QFN48)
part A pins: 4 PB12, 5 PA8, 6 PA7, 7 PA6, 9 PA5, 10 PA2, 12 PA1, 14 PD9, 15 PD8, 16 PD7, 17 PD6, 18 PB8, 19 PC15-OSC32_OUT, 20 PC14-OSC32_IN, 21 PC13, 23 PB4, 24 PB3, 25 PA15, 26 PA14-SWCLK, 27 PA13-SWDIO, 28 PA12, 29 PA11, 30 PB2, 31 PB1, 32 PB0, 33 PB15, 34 PH3-BOOT0, 36 NRST, 41 OSC_OUT, 42 OSC_IN, 46 PA10, 47 PA9, 48 PB14
part B pins: 1 VSSSMPS, 2 VDDSMPS, 3 VLXSMPS, 8 VDDA, 11 VDD, 13 VDDUSB, 22 VDD, 35 VDD, 39 VDDANA, 44 VDD, 45 VDD11, 49 VSS (ExPAD)
part C pins: 37 RF, 38 VDDHPA, 40 VDDRF, 43 VDDRFPA

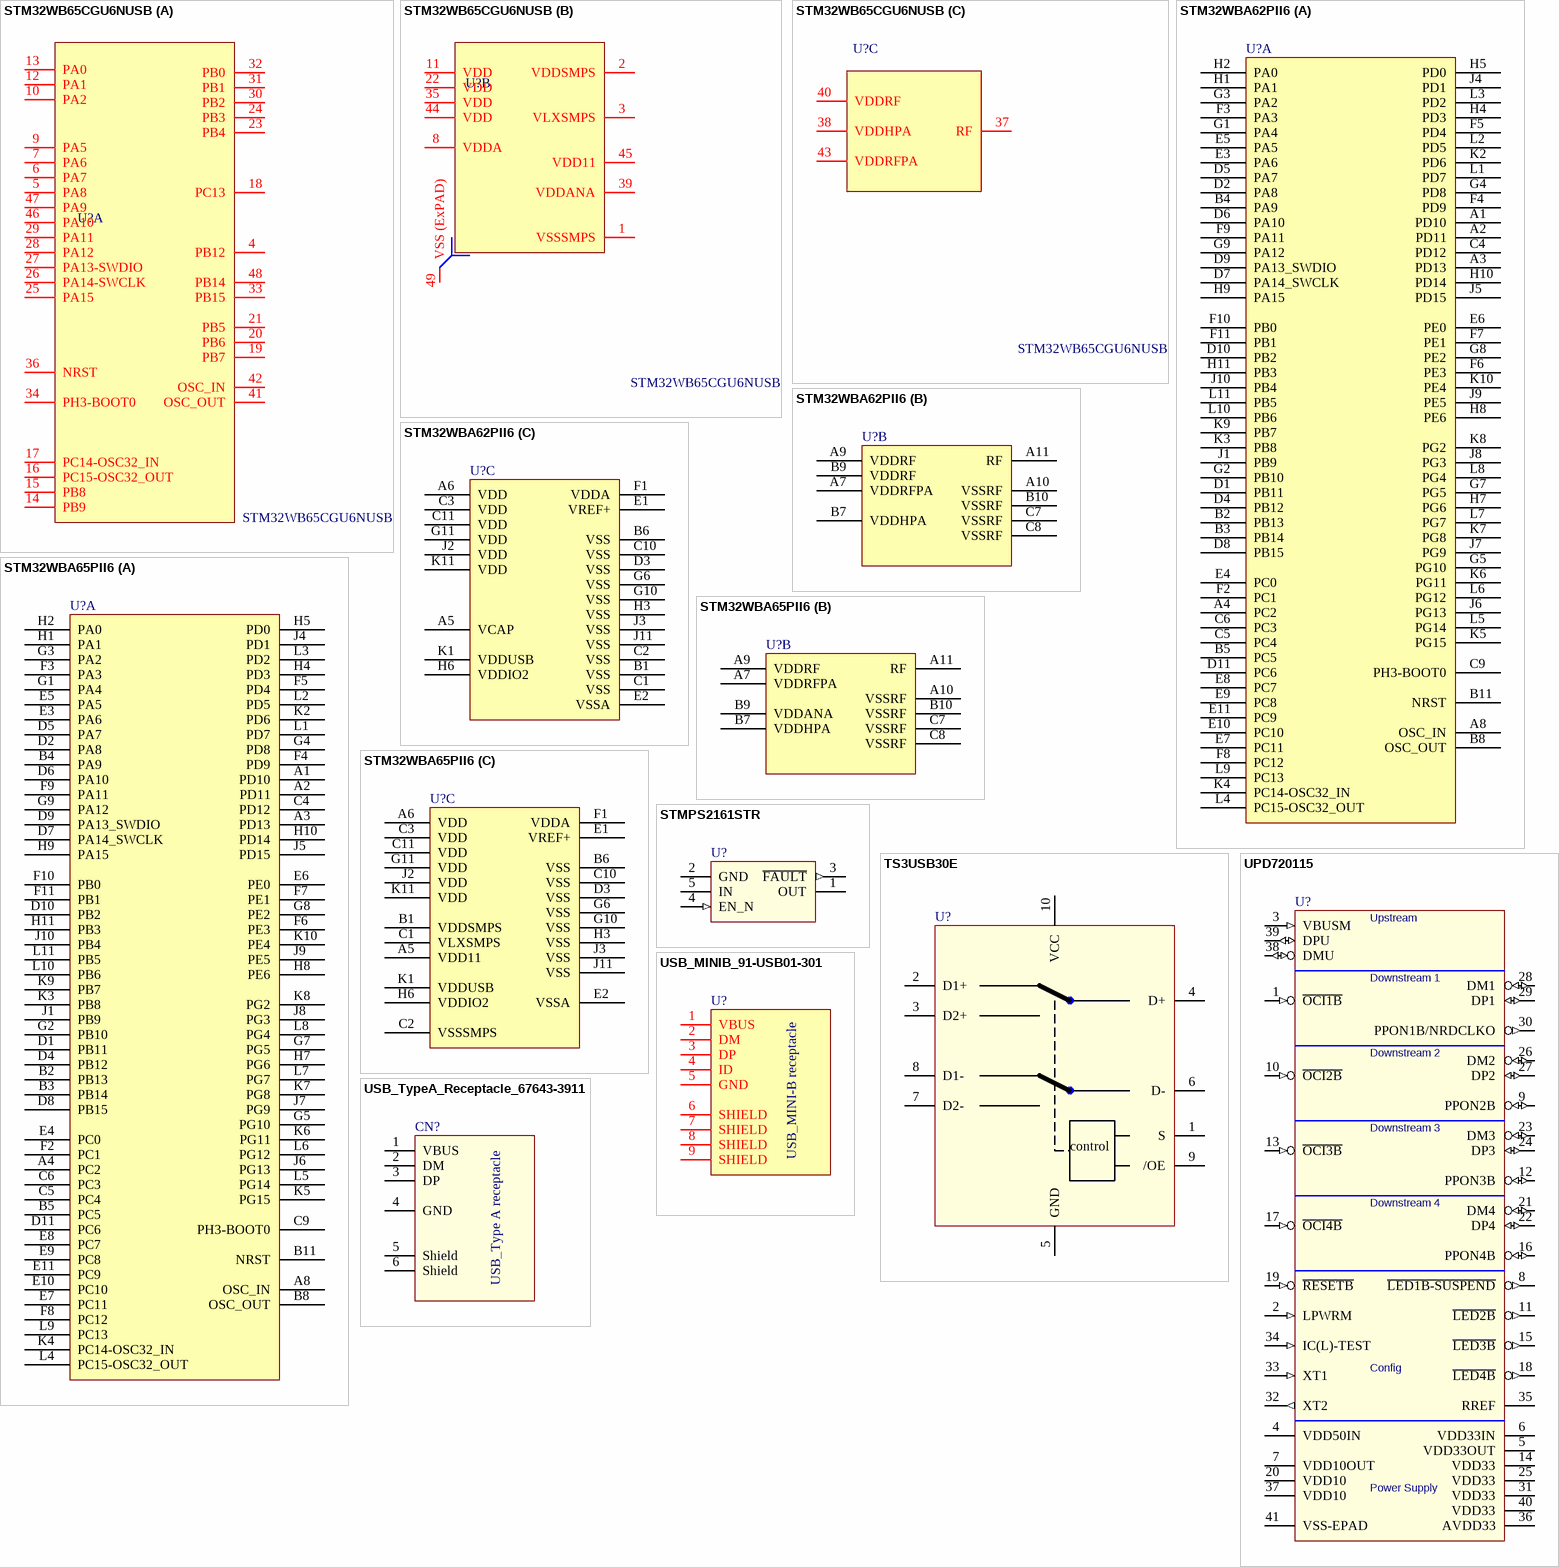
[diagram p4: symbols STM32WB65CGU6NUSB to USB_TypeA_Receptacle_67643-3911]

## STM32WB65CGU6NUSB
designator U?
STM32WB65CGU6NUSB  QFN48 no USB
footprint STM32WB65CGU6NUSB (STM32WB65CGU6   QFN48)
part A pins: 4 PB12, 5 PA8, 6 PA7, 7 PA6, 9 PA5, 10 PA2, 12 PA1, 13 PA0, 14 PB9, 15 PB8, 16 PC15-OSC32_OUT, 17 PC14-OSC32_IN, 18 PC13, 19 PB7, 20 PB6, 21 PB5, 23 PB4, 24 PB3, 25 PA15, 26 PA14-SWCLK, 27 PA13-SWDIO, 28 PA12, 29 PA11, 30 PB2, 31 PB1, 32 PB0, 33 PB15, 34 PH3-BOOT0, 36 NRST, 41 OSC_OUT, 42 OSC_IN, 46 PA10, 47 PA9, 48 PB14
part B pins: 1 VSSSMPS, 2 VDDSMPS, 3 VLXSMPS, 8 VDDA, 11 VDD, 22 VDD, 35 VDD, 39 VDDANA, 44 VDD, 45 VDD11, 49 VSS (ExPAD)
part C pins: 37 RF, 38 VDDHPA, 40 VDDRF, 43 VDDRFPA

## STM32WBA62PII6
designator U?
STM32WBA62 BGA121 reduced set of features; Internal_Part_Number: MCD-04262; Manufacturer: STMICROELECTRONICS; Manufacturer_Part_Number: STM32WBA62PII6; ECCN_EU: NEC; ECCN_US: EAR99
part A pins: A1 PD10, A2 PD11, A3 PD13, A4 PC2, A8 OSC_IN, B2 PB13, B3 PB14, B4 PA9, B5 PC5, B8 OSC_OUT, B11 NRST, C4 PD12, C5 PC4, C6 PC3, C9 PH3-BOOT0, D1 PB11, D2 PA8, D4 PB12, D5 PA7, D6 PA10, D7 PA14_SWCLK, D8 PB15, D9 PA13_SWDIO, D10 PB2, D11 PC6, E3 PA6, E4 PC0, E5 PA5, E6 PE0, E7 PC11, E8 PC7, E9 PC8, E10 PC10, E11 PC9, F2 PC1, F3 PA3, F4 PD9, F5 PD4, F6 PE3, F7 PE1, F8 PC12, F9 PA11, F10 PB0, F11 PB1, G1 PA4, G2 PB10, G3 PA2, G4 PD8, G5 PG10, G7 PG5, G8 PE2, G9 PA12, H1 PA1, H2 PA0, H4 PD3, H5 PD0, H7 PG6, H8 PE6, H9 PA15, H10 PD14, H11 PB3, J1 PB9, J4 PD1, J5 PD15, J6 PG13, J7 PG9, J8 PG3, J9 PE5, J10 PB4, K2 PD6, K3 PB8, K4 PC14-OSC32_IN, K5 PG15, K6 PG11, K7 PG8, K8 PG2, K9 PB7, K10 PE4, L1 PD7, L2 PD5, L3 PD2, L4 PC15-OSC32_OUT, L5 PG14, L6 PG12, L7 PG7, L8 PG4, L9 PC13, L10 PB6, L11 PB5
part B pins: A7 VDDRFPA, A9 VDDRF, A10 VSSRF, A11 RF, B7 VDDHPA, B9 VDDRF, B10 VSSRF, C7 VSSRF, C8 VSSRF
part C pins: A5 VCAP, A6 VDD, B1 VSS, B6 VSS, C1 VSS, C2 VSS, C3 VDD, C10 VSS, C11 VDD, D3 VSS, E1 VREF+, E2 VSSA, F1 VDDA, G6 VSS, G10 VSS, G11 VDD, H3 VSS, H6 VDDIO2, J2 VDD, J3 VSS, J11 VSS, K1 VDDUSB, K11 VDD

## STM32WBA65PII6
designator U?
STM32WBA65 BGA121 full set of features + SMPS; Internal_Part_Number: MCD-04262; Manufacturer: STMICROELECTRONICS; Manufacturer_Part_Number: STM32WBA65PII6; ECCN_EU: NEC; ECCN_US: EAR99
part A pins: A1 PD10, A2 PD11, A3 PD13, A4 PC2, A8 OSC_IN, B2 PB13, B3 PB14, B4 PA9, B5 PC5, B8 OSC_OUT, B11 NRST, C4 PD12, C5 PC4, C6 PC3, C9 PH3-BOOT0, D1 PB11, D2 PA8, D4 PB12, D5 PA7, D6 PA10, D7 PA14_SWCLK, D8 PB15, D9 PA13_SWDIO, D10 PB2, D11 PC6, E3 PA6, E4 PC0, E5 PA5, E6 PE0, E7 PC11, E8 PC7, E9 PC8, E10 PC10, E11 PC9, F2 PC1, F3 PA3, F4 PD9, F5 PD4, F6 PE3, F7 PE1, F8 PC12, F9 PA11, F10 PB0, F11 PB1, G1 PA4, G2 PB10, G3 PA2, G4 PD8, G5 PG10, G7 PG5, G8 PE2, G9 PA12, H1 PA1, H2 PA0, H4 PD3, H5 PD0, H7 PG6, H8 PE6, H9 PA15, H10 PD14, H11 PB3, J1 PB9, J4 PD1, J5 PD15, J6 PG13, J7 PG9, J8 PG3, J9 PE5, J10 PB4, K2 PD6, K3 PB8, K4 PC14-OSC32_IN, K5 PG15, K6 PG11, K7 PG8, K8 PG2, K9 PB7, K10 PE4, L1 PD7, L2 PD5, L3 PD2, L4 PC15-OSC32_OUT, L5 PG14, L6 PG12, L7 PG7, L8 PG4, L9 PC13, L10 PB6, L11 PB5
part B pins: A7 VDDRFPA, A9 VDDRF, A10 VSSRF, A11 RF, B7 VDDHPA, B9 VDDANA, B10 VSSRF, C7 VSSRF, C8 VSSRF
part C pins: A5 VDD11, A6 VDD, B1 VDDSMPS, B6 VSS, C1 VLXSMPS, C2 VSSSMPS, C3 VDD, C10 VSS, C11 VDD, D3 VSS, E1 VREF+, E2 VSSA, F1 VDDA, G6 VSS, G10 VSS, G11 VDD, H3 VSS, H6 VDDIO2, J2 VDD, J3 VSS, J11 VSS, K1 VDDUSB, K11 VDD

## STMPS2161STR
designator U?
pins: 1 OUT, 2 GND, 3 ~{FAULT} (out), 4 EN_N (in), 5 IN

## TS3USB30E
designator U?
pins: 1 S, 2 D1+, 3 D2+, 4 D+, 5 GND, 6 D-, 7 D2-, 8 D1-, 9 /OE, 10 VCC

## UPD720115
designator U?
pins: 1 ~{OCI1B} (in), 2 LPWRM (in), 3 VBUSM (in), 4 VDD50IN (power), 5 VDD33OUT (power), 6 VDD33IN (power), 7 VDD10OUT (power), 8 ~{LED1B-SUSPEND} (out), 9 PPON2B (io), 10 ~{OCI2B} (in), 11 ~{LED2B} (out), 12 PPON3B (io), 13 ~{OCI3B} (in), 14 VDD33 (power), 15 ~{LED3B} (out), 16 PPON4B (io), 17 ~{OCI4B} (in), 18 ~{LED4B} (out), 19 ~{RESETB} (in), 20 VDD10 (power), 21 DM4 (io), 22 DP4 (io), 23 DM3 (io), 24 DP3 (io), 25 VDD33 (power), 26 DM2 (io), 27 DP2 (io), 28 DM1 (io), 29 DP1 (io), 30 PPON1B/NRDCLKO (out), 31 VDD33 (power), 32 XT2 (out), 33 XT1 (in), 34 IC(L)-TEST (in), 35 RREF, 36 AVDD33 (power), 37 VDD10 (power), 38 DMU (io), 39 DPU (io), 40 VDD33 (power), 41 VSS-EPAD (power)

## USB_MINIB_91-USB01-301
designator U?
pins: 1 VBUS, 2 DM, 3 DP, 4 ID, 5 GND, 6 SHIELD, 7 SHIELD, 8 SHIELD, 9 SHIELD

## USB_TypeA_Receptacle_67643-3911
designator CN?
pins: 1 VBUS, 2 DM, 3 DP, 4 GND, 5 Shield, 6 Shield

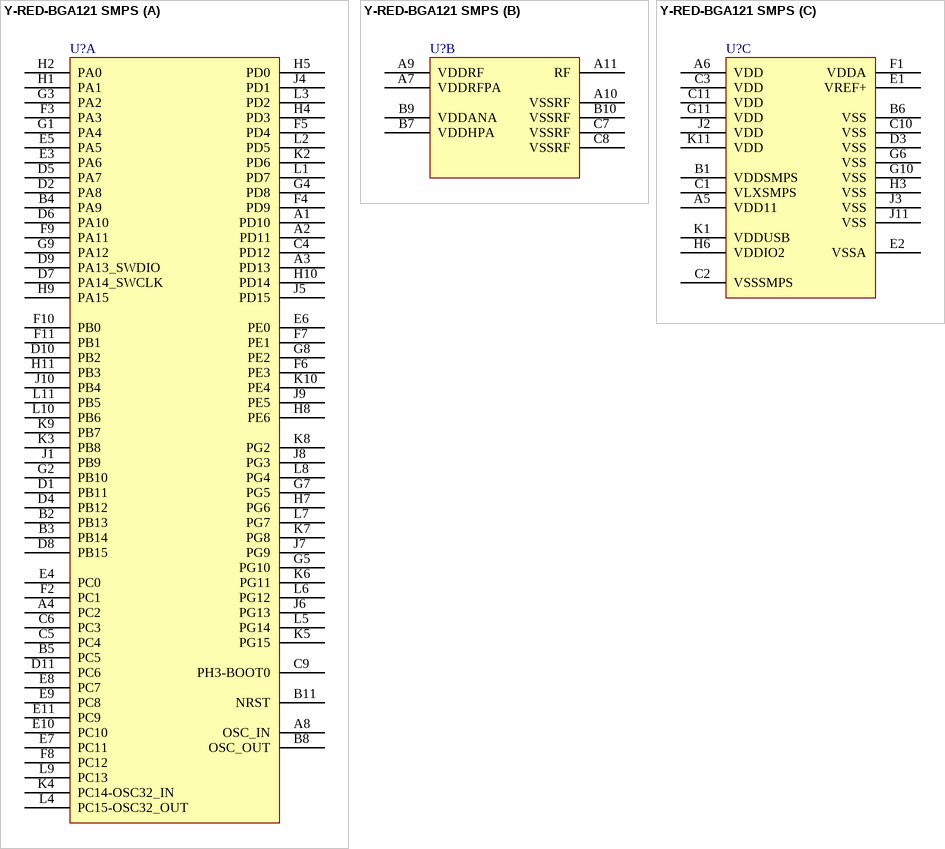
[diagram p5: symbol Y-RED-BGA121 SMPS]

## Y-RED-BGA121 SMPS
designator U?, comment Y-RED-BGA121  (value not drawn)
Socket  BGA121 SMPS version; Internal_Part_Number: MCD-04416; Manufacturer: STMICROELECTRONICS; Manufacturer_Part_Number: STM32WBA65Px; ECCN_EU: NEC; ECCN_US: EAR99
footprint Y-RED-BGA121 (Socket BGA121 SMPS)
part A pins: A1 PD10, A2 PD11, A3 PD13, A4 PC2, A8 OSC_IN, B2 PB13, B3 PB14, B4 PA9, B5 PC5, B8 OSC_OUT, B11 NRST, C4 PD12, C5 PC4, C6 PC3, C9 PH3-BOOT0, D1 PB11, D2 PA8, D4 PB12, D5 PA7, D6 PA10, D7 PA14_SWCLK, D8 PB15, D9 PA13_SWDIO, D10 PB2, D11 PC6, E3 PA6, E4 PC0, E5 PA5, E6 PE0, E7 PC11, E8 PC7, E9 PC8, E10 PC10, E11 PC9, F2 PC1, F3 PA3, F4 PD9, F5 PD4, F6 PE3, F7 PE1, F8 PC12, F9 PA11, F10 PB0, F11 PB1, G1 PA4, G2 PB10, G3 PA2, G4 PD8, G5 PG10, G7 PG5, G8 PE2, G9 PA12, H1 PA1, H2 PA0, H4 PD3, H5 PD0, H7 PG6, H8 PE6, H9 PA15, H10 PD14, H11 PB3, J1 PB9, J4 PD1, J5 PD15, J6 PG13, J7 PG9, J8 PG3, J9 PE5, J10 PB4, K2 PD6, K3 PB8, K4 PC14-OSC32_IN, K5 PG15, K6 PG11, K7 PG8, K8 PG2, K9 PB7, K10 PE4, L1 PD7, L2 PD5, L3 PD2, L4 PC15-OSC32_OUT, L5 PG14, L6 PG12, L7 PG7, L8 PG4, L9 PC13, L10 PB6, L11 PB5
part B pins: A7 VDDRFPA, A9 VDDRF, A10 VSSRF, A11 RF, B7 VDDHPA, B9 VDDANA, B10 VSSRF, C7 VSSRF, C8 VSSRF
part C pins: A5 VDD11, A6 VDD, B1 VDDSMPS, B6 VSS, C1 VLXSMPS, C2 VSSSMPS, C3 VDD, C10 VSS, C11 VDD, D3 VSS, E1 VREF+, E2 VSSA, F1 VDDA, G6 VSS, G10 VSS, G11 VDD, H3 VSS, H6 VDDIO2, J2 VDD, J3 VSS, J11 VSS, K1 VDDUSB, K11 VDD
